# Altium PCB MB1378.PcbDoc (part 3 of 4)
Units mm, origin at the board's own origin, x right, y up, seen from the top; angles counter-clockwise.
Board outline 54.22 x 80.1 mm, 4 copper layers (Top Layer, L2-GND, L3, Bottom Layer), stack 0.771 mm thick; 206 components, 159 nets, 727 pads, 330 vias.
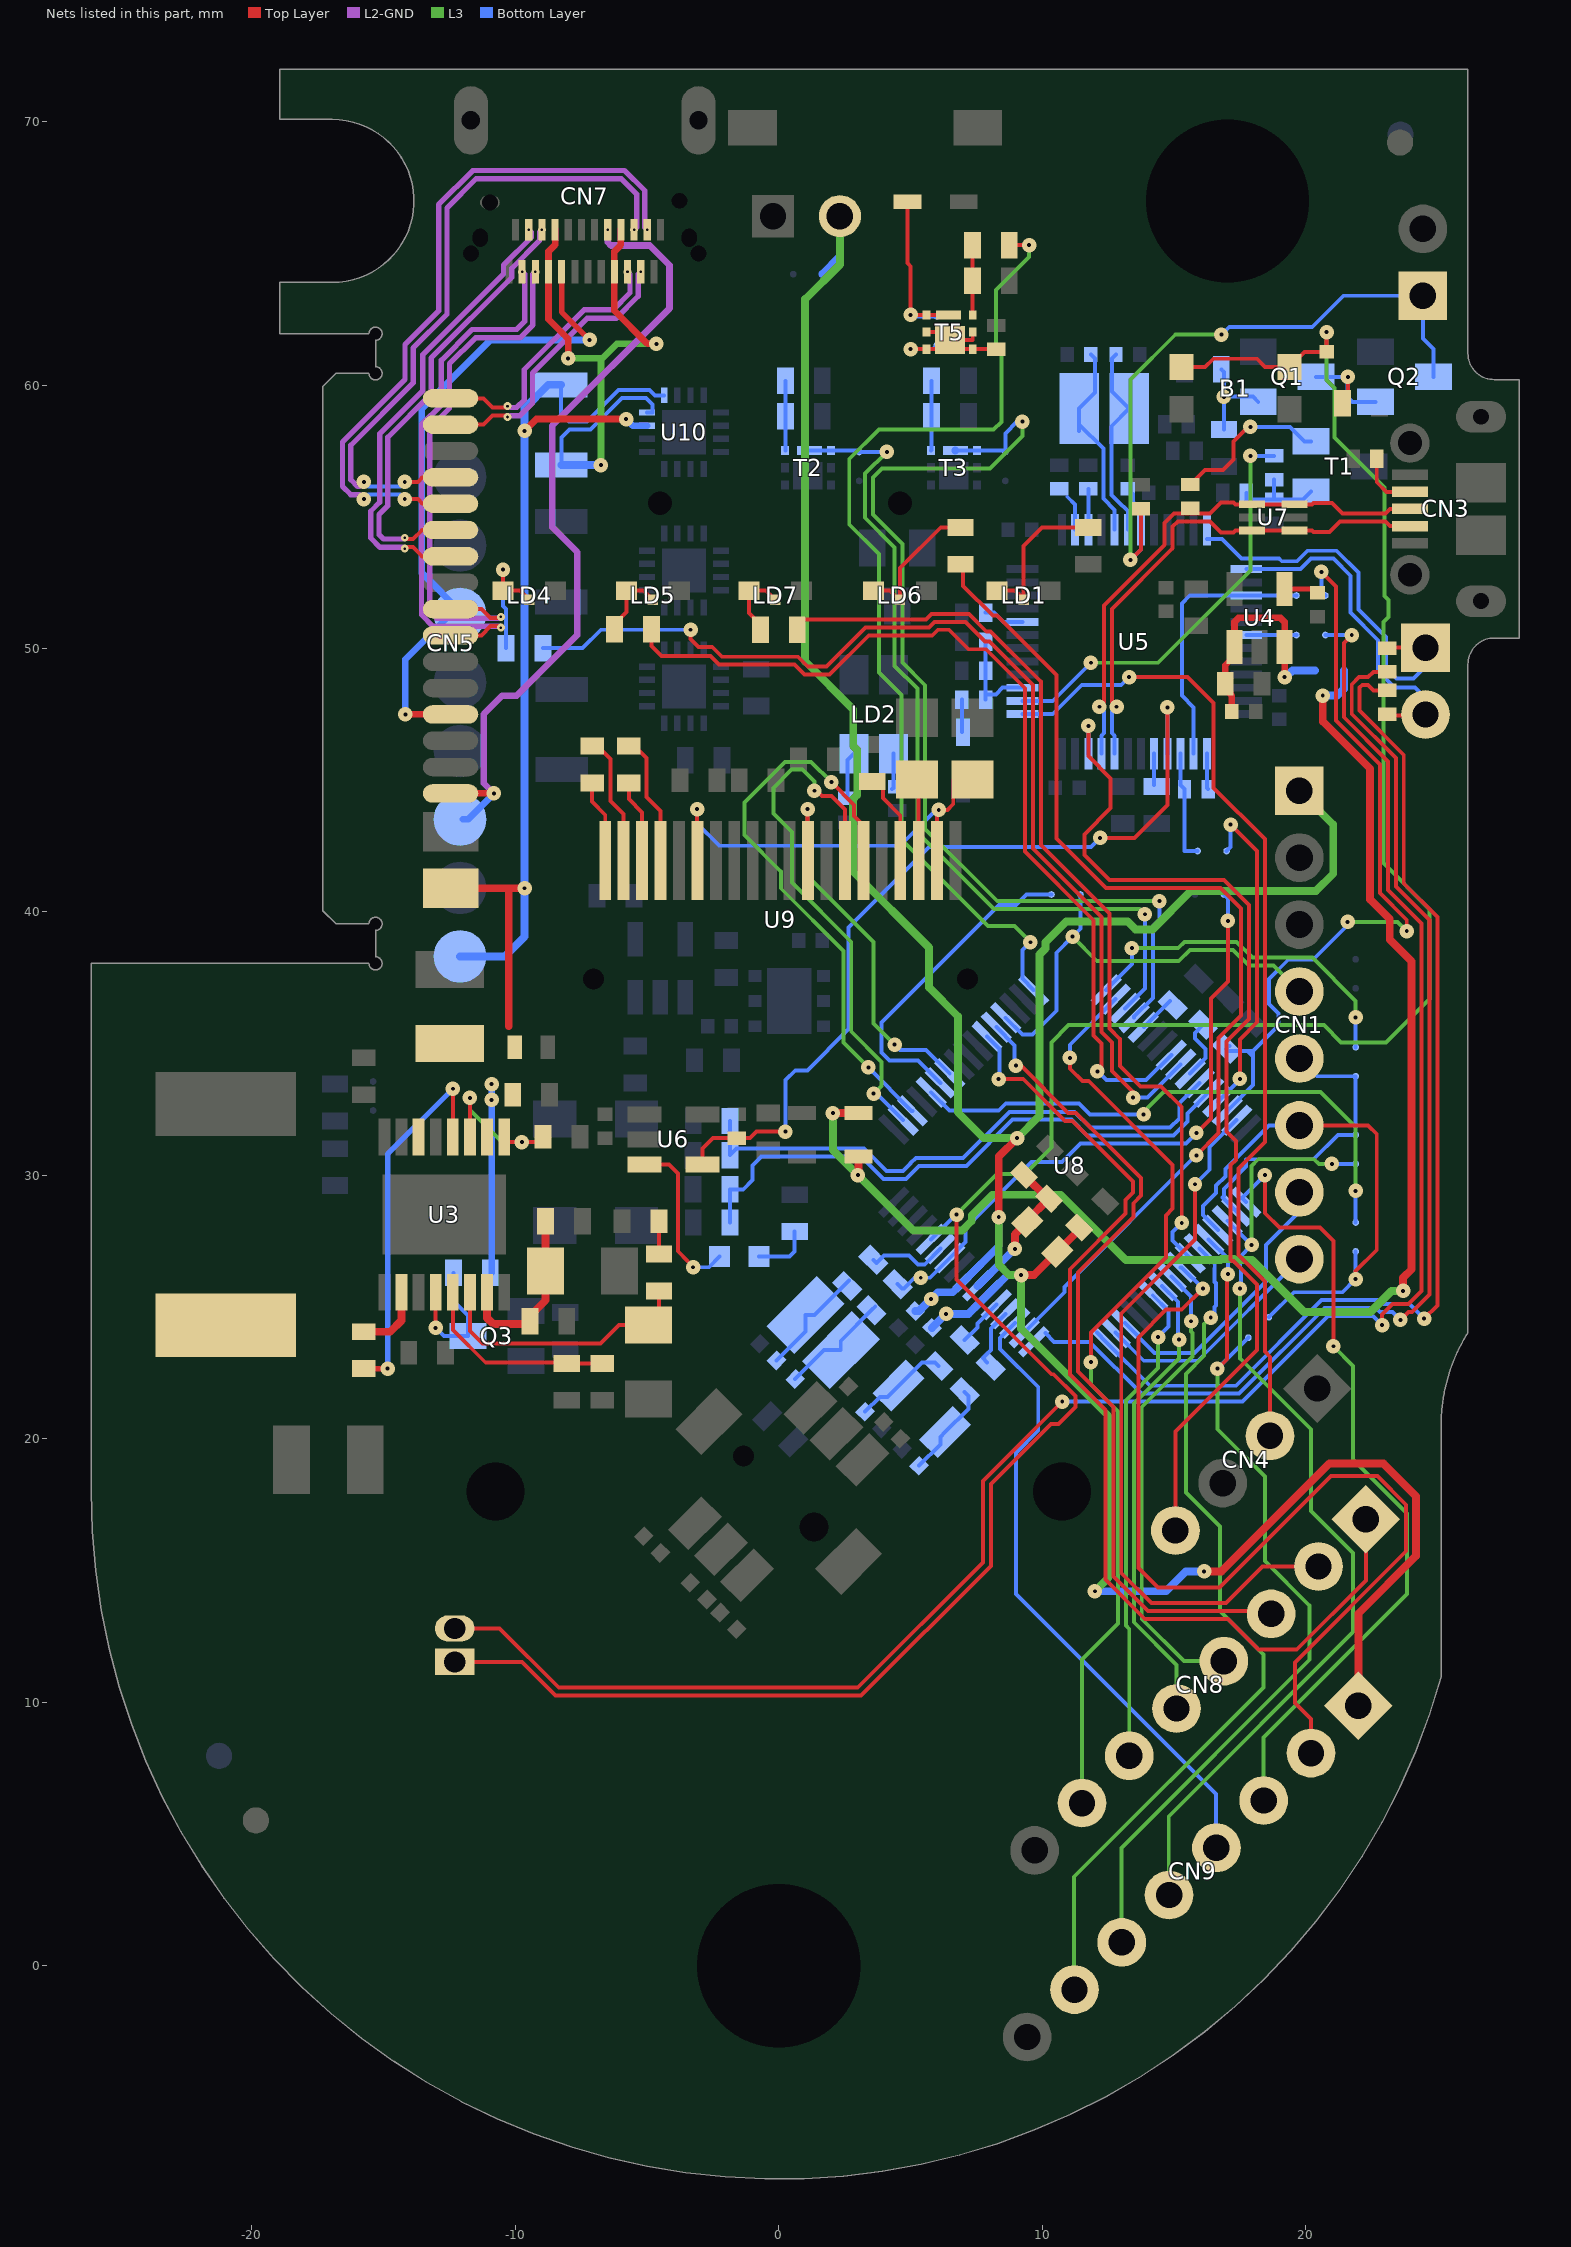
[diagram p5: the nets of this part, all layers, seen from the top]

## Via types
v1: diameter 0.55, hole 0.15, Top Layer to Bottom Layer, 308 vias
v2: diameter 0.3, hole 0.1, Top Layer to L2-GND, 22 vias

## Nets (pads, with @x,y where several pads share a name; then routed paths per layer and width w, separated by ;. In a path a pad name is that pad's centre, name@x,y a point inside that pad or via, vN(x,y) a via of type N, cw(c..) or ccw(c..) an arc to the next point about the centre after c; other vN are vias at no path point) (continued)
NetC9_1: C9.1 U3.12 | length 14.4
  Top Layer w0.15: U3.12@-12.372,31.462 v1(-12.372,33.287)
  Top Layer w0.2: C9.1@-15.747,22.662 v1(-14.847,22.662)
  Bottom Layer w0.2: v1(-14.847,22.662) -14.847,30.812 v1(-12.372,33.287)
NetC9_2: C9.2 L1.2 U3.2 | length 2.7
  Top Layer w0.3: C9.2@-15.747,24.062 -14.747,24.062 -14.322,24.487 U3.2@-14.322,25.562
NetC10_2: C10.2 R6.1 R10.2 U3.7 | length 6.8
  Top Layer w0.3: U3.7@-11.072,25.562 -11.072,24.587 -10.847,24.362 -9.472,24.362 -9.472,24.637 -8.847,25.262 C10.2@-8.847,26.362 R10.2@-8.847,28.262
NetC15_2: C15.2 R9.2 U3.5 | length 7.6
  Top Layer w0.15: U3.5@-12.372,25.562 -12.372,24.137 -11.122,22.887 -7.922,22.887 -7.897,22.862 C15.2@-6.697,22.862
NetC16_2: C16.2 U3.9 U3.11 | length 5.9
  Top Layer w0.15: U3.11@-11.722,31.462 v1(-11.722,32.937) ; U3.9@-10.372,31.262 C16.2@-8.897,31.262
  L3 w0.15: v1(-11.722,32.937) -11.722,32.487 -10.497,31.262 v1(-9.747,31.262)
NetC17_2: C17.2 R7.1 | length 1.2
  Top Layer w0.15: R7.1@-4.547,27.012 C17.2@-4.547,28.262
NetC18_2: C18.2 R7.2 U3.6 | length 10.1
  Top Layer w0.15: U3.6@-11.722,25.562 -11.722,24.087 -11.247,23.612 -6.768,23.612 -6.068,24.312 -5.697,24.312 -5.197,24.812 -4.697,24.812 -4.547,24.962 R7.2@-4.547,25.612
NetC21_1: C21.1 C22.2 SB1.2 U4.1 U4.3 | length 8.9
  Top Layer w0.25: C22.2@17.203,47.612 17.203,48.212 16.953,48.462 16.953,49.362 17.303,49.712 U4.1@17.303,50.062 17.303,51.012 17.453,51.162 19.053,51.162 19.203,51.012 U4.3@19.203,50.062 19.203,49.062 v1@19.303,48.962
  Bottom Layer w0.3: v1@19.303,48.962 19.503,49.162 SB1.2@20.353,49.162
  other v1: 19.203,48.912
NetC25_2: C25.2 U4.4 | length 1.3
  Top Layer w0.2: U4.4@19.303,52.262 C25.2@20.553,52.262
NetC34_1: C34.1 U9.2 | length 5.2
  Top Layer w0.15: C34.1@-7.087,46.299 -6.884,46.299 -6.387,45.802 -6.387,44.212 -5.887,43.712 U9.2@-5.887,41.949 U9.2@-5.887,41.749
NetC34_2: C34.2 U9.1 | length 3.4
  Top Layer w0.15: C34.2@-7.087,44.899 -7.087,44.187 -6.587,43.687 U9.1@-6.587,41.949 U9.1@-6.587,41.749
NetC35_1: C35.1 U9.3 | length 3.4
  Top Layer w0.15: C35.1@-5.687,44.899 -5.687,44.282 -5.187,43.782 U9.3@-5.187,41.949 U9.3@-5.187,41.749
NetC35_2: C35.2 U9.4 | length 5.2
  Top Layer w0.15: C35.2@-5.687,46.299 -5.474,46.299 -5.017,45.842 -5.017,44.357 -4.487,43.827 U9.4@-4.487,41.949 U9.4@-4.487,41.749
NetC36_1: C36.1 U9.6 U9.19 | length 17.2
  Top Layer w0.15: v1(-3.1,43.9) -3.1,41.962 U9.6@-3.087,41.949 U9.6@-3.087,41.749 ; U9.19@6.013,41.749 U9.19@6.013,41.949 6.013,43.818 6.07,43.875 v1(6.075,43.875) 6.399,43.875 6.625,44.101 6.625,44.987 C36.1@7.353,44.987
  Bottom Layer w0.15: v1(-3.1,43.9) -3.1,43.365 -2.247,42.512 4.603,42.512 5.965,43.875 v1(6.075,43.875)
NetC39_1: C39.1 R36.2 X2.1 | length 3.6
  Bottom Layer w0.15: C39.1@5.325,18.978 6.138,19.791 6.138,20.074 X2.1@6.315,20.251 7.199,21.135 7.199,21.63 R36.2@7.057,21.771
NetC40_1: C40.1 R39.2 X2.2 | length 3.6
  Bottom Layer w0.15: C40.1@3.274,21.029 3.84,21.594 4.123,21.594 5.431,22.902 5.926,22.902 R39.2@6.067,22.761
NetC41_1: C41.1 U9.18 | length 3.2
  Top Layer w0.15: U9.18@5.313,41.749 C41.1@5.313,44.974
NetC42_1: C42.1 R41.2 X3.2 | length 4.4
  Bottom Layer w0.15: C42.1@0.623,22.266 1.719,23.362 X3.2@2.355,23.362 2.355,23.716 R41.2@3.522,24.882 R41.2@3.663,25.024
NetC43_1: C43.1 R44.2 X3.1 | length 4.4
  Bottom Layer w0.15: C43.1@-0.084,22.973 1.012,24.069 X3.1@1.012,24.706 1.365,24.706 R44.2@2.673,26.014
NetD3_1: D3.1 SB10.2 T5.4 T5.7 | length 6.8
  Top Layer w0.15: D3.1@4.883,66.962 4.883,64.632 5.003,64.512 v1(5.003,62.662) T5.4@5.615,62.662 T5.7@6.44,62.662
  Bottom Layer w0.15: v1(5.003,62.662) 5.053,62.612 SB10.2@6.003,62.612
NetD4_2: D4.2 R12.2 | length 1.2
  Bottom Layer w0.15: D4.2@6.953,46.832 R12.2@6.953,48.062
NetD5_2: D5.2 D6.2 SB1.1 | length 54.6
  Top Layer w0.3: v1(2.053,32.362) D5.2@3.023,32.362 ; v1(3.003,30.012) 3.023,30.032 D6.2@3.023,30.712 ; v1(20.653,48.212) 20.653,47.236 22.453,45.436 22.453,40.476 23.195,39.733 23.195,38.95 24.028,38.117 24.028,26.437 23.703,26.112 v1(23.703,25.612)
  L3 w0.3: v1(2.053,32.362) 2.053,30.962 v1(3.003,30.012) 5.115,27.9 6.953,27.9 7.328,28.274 7.328,28.478 8.112,29.262 10.703,29.262 13.178,26.787 16.774,26.787 16.812,26.825 17.288,26.825 17.326,26.787 17.963,26.787 19.938,24.812 22.466,24.812 23.266,25.612 v1(23.703,25.612)
  Bottom Layer w0.3: v1(20.653,48.212) 21.203,48.212 21.453,48.462 SB1.1@21.453,49.162
NetJP2_2: JP2.2 SB4.2 | length 73.5
  Top Layer w0.15: JP2.2@-12.3,12.8 -10.6,12.8 -8.35,10.55 3,10.55 7.75,15.3 7.75,18.4 v1(10.762,21.412) ; v1(21.753,50.512) 21.453,50.212 21.453,47.391 23.128,45.716 23.128,40.839 24.403,39.564 24.403,25.605 23.91,25.112 23.296,25.112 22.903,24.719 v1(22.903,24.312)
  Bottom Layer w0.15: v1(10.762,21.412) 17.601,21.412 20.851,24.662 22.553,24.662 v1(22.903,24.312) ; SB4.2@20.753,50.512 v1(21.753,50.512)
NetLD1_1: LD1.1 R3.1 | length 5.9
  Top Layer w0.15: LD1.1@8.293,52.199 8.966,52.199 LD1.1@9.293,51.872 ; LD1.1@9.293,51.849 LD1.1@9.293,51.872 ; R3.1@11.75,54.6 10,54.6 9.293,53.893 LD1.1@9.293,51.872
NetLD2_2: LD2.2 R24.1 | length 1.8
  Bottom Layer w0.15: R24.1@2.603,44.312 2.603,45.762 LD2.2@2.853,46.012
NetLD2_3: LD2.3 R26.1 | length 1.4
  Bottom Layer w0.15: R26.1@4.303,44.662 4.353,44.712 LD2.3@4.353,46.012
NetLD3_1: LD3.1 R31.2 | length 2.2
  Bottom Layer w0.15: LD3.1@-0.747,26.912 0.403,26.912 0.603,27.112 R31.2@0.603,27.862
NetLD3_2: LD3.2 U6.3 | length 6.1
  Top Layer w0.15: U6.3@-5.097,30.412 -4.166,30.412 -3.822,30.069 -3.822,27.119 -3.457,26.753
  Bottom Layer w0.15: v1(-3.247,26.512) -2.647,26.512 LD3.2@-2.247,26.912
NetLD4_1: LD4.1 R32.1 | length 4.9
  Top Layer w0.15: v1(-10.467,52.992) LD4.1@-10.467,52.199 -9.817,52.199 LD4.1@-9.481,51.862
  Bottom Layer w0.15: v1(-10.467,52.992) -10.467,51.612 -10.347,51.492 R32.1@-10.347,50.012
NetLD5_1: LD5.1 R33.1 | length 2.6
  Top Layer w0.15: R33.1@-6.247,50.912 -5.777,51.382 LD5.1@-5.777,52.199 -5.134,52.199 LD5.1@-4.797,51.862
NetLD6_1: LD6.1 R52.1 | length 5.3
  Top Layer w0.15: LD6.1@3.602,52.199 4.216,52.199 4.553,51.862 LD6.1@4.602,51.862 ; LD6.1@4.602,51.849 LD6.1@4.602,51.862 ; R52.1@6.9,54.6 6.15,54.6 4.602,53.052 LD6.1@4.602,51.862
NetLD7_1: LD7.1 R61.1 | length 2.9
  Top Layer w0.15: R61.1@-0.697,50.712 -0.697,50.912 -1.137,51.352 LD7.1@-1.137,52.199 -0.484,52.199 LD7.1@-0.097,51.812
NetQ1_1: Q1.1 R42.2 R43.2 | length 3.7
  Bottom Layer w0.15: R43.2@16.8,60.6 16.903,60.497 v1@16.903,59.612 ; R42.2@16.903,58.312 v1(16.903,59.55) v1@16.903,59.612 ; Q1.1@18.203,59.362 18.003,59.562 16.953,59.562 v1@16.903,59.612
NetQ1_3: Q1.3 Q2.1 R51.1 | length 4.2
  Top Layer w0.15: R51.1@21.403,59.312 21.603,59.512 v1(21.603,60.312)
  Bottom Layer w0.15: Q1.3@20.403,60.312 v1(21.603,60.312) 21.6,60.31 21.6,59.55 21.788,59.362 Q2.1@22.653,59.362
NetQ3_3: Q3.3 R8.1 U3.4 | length 5.3
  Top Layer w0.15: v1(-13.022,24.212) U3.4@-13.022,25.562
  Bottom Layer w0.15: v1(-13.022,24.212) -12.71,23.9 Q3.3@-11.8,23.9 -11.8,24.675 -12.35,25.225 R8.1@-12.35,26.3
NetR14_2: R14.2 U5.44 | length 1.5
  Bottom Layer w0.15: R14.2@7.853,51.362 8.177,51.362 8.527,51.012 U5.44@9.253,51.012
NetR15_1: R15.1 U5.2 | length 1.4
  Bottom Layer w0.15: 10.953,55.762 11.253,55.462 U5.2@11.253,54.512
NetR16_2: R16.2 U5.3 | length 1.6
  Bottom Layer w0.15: U5.3@11.753,54.512 R16.2@11.753,56.062
NetR18_1: R18.1 U5.29 | length 1.2
  Bottom Layer w0.15: R18.1@14.253,44.812 U5.29@14.253,46.012
NetR25_1: R25.1 R27.2 R28.2 T1.1 | length 3.6
  Bottom Layer w0.15: R28.2@17.753,55.912 17.753,55.662 R27.2@18.803,55.662 ; R25.1@18.803,56.412 R27.2@18.803,55.662 ; T1.1@20.203,55.962 19.903,55.662 R27.2@18.803,55.662
NetR29_2: R29.2 T1.2 | length 6.1
  Top Layer w0.15: R29.2@15.628,56.226 16.174,56.773 16.863,56.773 17.268,57.177 17.268,57.866 17.814,58.412 v1(17.903,58.412)
  Bottom Layer w0.15: v1(17.903,58.412) 19.403,58.412 19.953,57.862 T1.2@20.203,57.862
NetR35_2: R35.2 U8.37 | length 1.4
  Bottom Layer w0.15: U8.37@13.871,35.63 R35.2@14.858,36.617
NetR38_2: R38.2 U8.42 | length 2.4
  Bottom Layer w0.15: U8.42@15.613,33.863 16.2,34.449 16.2,34.8 16,35 15.8,35.2 15.8,35.41 R38.2@16.108,35.717
NetR40_2: R40.2 U9.17 | length 3.9
  Top Layer w0.15: R40.2@3.55,44.95 3.955,44.95 3.955,44.325 4.613,43.667 U9.17@4.613,41.949 U9.17@4.613,41.749
NetR52_2: R52.2 U8.2 | length 39.6
  Top Layer w0.15: R52.2@6.9,53.2 7.003,53.097 7.003,52.374 8.127,51.25 8.288,51.25 10.55,48.988 10.55,42.791 12.428,40.912 16.778,40.912 17.553,40.138 17.553,36.061 16.703,35.211 16.703,31.612 v1(15.853,30.762)
  Bottom Layer w0.15: U8.2@9.32,24.034 10.849,25.562 10.849,25.766 15.845,30.762 v1(15.853,30.762)
NetR55_1: R55.1 R62.2 T5.3 | length 2.6
  Top Layer w0.15: T5.3@7.353,62.675 R55.1@7.353,63.962 R62.2@7.353,65.312
NetR56_1: R56.1 SB10.1 T5.1 T5.2 T5.5 T5.6 T5.8 | length 6.7
  Top Layer w0.15: v1(5.003,61.362) T5.6@5.615,61.362 T5.1@7.365,61.362 R56.1@8.253,61.362 ; T5.5@5.615,62.012 6.503,62.012 T5.8@6.503,61.712 7.365,61.712 T5.2@7.365,62.012
  Bottom Layer w0.15: v1(5.003,61.362) 5.853,61.362 SB10.1@6.003,61.512
NetR57_1: R57.1 R59.2 T2.3 | length 2.6
  Bottom Layer w0.15: T2.3@0.253,57.525 R57.1@0.253,58.812 R59.2@0.253,60.162
NetR58_1: R58.1 R60.2 T3.3 | length 2.7
  Bottom Layer w0.15: T3.3@5.778,57.512 5.803,57.537 R58.1@5.803,58.812 R60.2@5.803,60.162
NRST: B1.1 B1.3 C44.2 JP2.1 U8.12 | length 99.1
  Top Layer w0.15: JP2.1@-12.3,11.53 -9.754,11.53 -8.474,10.25 3.124,10.25 8.05,15.176 8.05,18.276 10.337,20.562 10.62,20.562 11.262,21.205 11.262,21.62 10.432,22.45 10.35,22.45 6.753,26.047 v1(6.753,28.512) ; B1.3@15.288,60.687 16.187,60.687 16.5,61 18.15,61 18.463,60.687 B1.1@19.388,60.687 19.963,61.262 C44.2@20.803,61.262 v1(20.803,62.012)
  L3 w0.15: v1(6.753,28.512) 8.29,30.05 9.35,30.05 10.35,31.05 10.35,35.05 11,35.7 20.7,35.7 21.35,35.05 23.05,35.05 24.703,36.703 24.703,40.097 22.95,41.85 22.95,47.979 22.953,47.982 22.953,51.003 23.153,51.203 23.153,51.837 22.988,52.002 22.988,56.12 21.103,58.005 21.103,59.897 20.803,60.197 v1(20.803,62.012)
  Bottom Layer w0.15: U8.12@5.785,27.569 v1@6.74,28.525
OSC_IN: C20.1 U5.5 X1.2 | length 7.8
  Bottom Layer w0.15: X1.2@11.403,58.262 X1.2@11.403,58.512 ; C20.1@11.853,61.162 12.003,61.012 12.003,59.712 X1.2@11.403,59.112 X1.2@11.403,58.512 ; U5.5@12.753,54.512 12.753,55.263 12.328,55.688 12.328,57.587 X1.2@11.403,58.512
OSC_OUT: C19.1 U5.6 X1.1 | length 7.5
  Bottom Layer w0.15: C19.1@12.803,61.162 12.653,61.012 12.653,59.762 X1.1@13.303,59.112 12.628,58.437 12.628,55.834 12.879,55.582 12.883,55.582 13.253,55.212 U5.6@13.253,54.512
PA4: SB12.1 U8.21 | length 21.3
  L3 w0.15: v1(13.853,32.312) 13.853,32.412 14.603,33.162 20.575,33.162 21.903,31.835 v1(21.903,29.412)
  Bottom Layer w0.15: U8.21@5.785,33.155 6.478,32.462 8.353,32.462 8.618,32.728 11.403,32.728 11.818,32.312 v1(13.853,32.312) ; SB12.1@21.903,28.212 v1(21.903,29.412)
PA5: SB11.1 U8.22 | length 12.3
  Bottom Layer w0.15: U8.22@6.138,33.509 5.285,34.362 4.203,34.362 3.903,34.662 3.903,35.803 8.362,40.262 9.003,40.262 9.403,40.662 SB11.1@10.353,40.662
PA15: CN8.2 U8.47 | length 27.5
  Top Layer w0.15: v1(15.803,29.662) 15.803,27.561 13.003,24.761 13.003,14.903 14.144,13.762 16.981,13.762 18.37,15.151 CN8.2@20.491,15.151
  Bottom Layer w0.15: v1(15.803,29.662) 16.353,30.212 16.353,31.066 U8.47@17.381,32.095
PB0: CN8.1 U8.27 | length 39.6
  Top Layer w0.15: v1(8.35,33.65) 9.282,33.65 10.864,32.069 11.153,32.069 13.453,29.77 13.453,29.355 13.163,29.066 13.163,28.548 11.053,26.437 11.053,22.438 12.403,21.088 12.403,14.655 13.895,13.162 17.053,13.162 18.215,12 19.666,12 22.287,14.621 CN8.1@22.287,16.947
  Bottom Layer w0.15: U8.27@7.906,35.277 8.378,34.804 8.378,33.678 v1(8.35,33.65)
PB1: CN8.3 U8.28 | length 31.5
  Top Layer w0.15: v1(9.003,34.162) 9.194,34.162 10.988,32.369 11.278,32.369 13.753,29.894 13.753,29.231 13.463,28.942 13.463,28.423 11.353,26.312 11.353,22.562 12.703,21.212 12.703,14.779 14.019,13.462 18.587,13.462 CN8.3@18.695,13.354
  Bottom Layer w0.15: U8.28@8.26,35.63 8.952,34.937 8.952,34.213 v1(9.003,34.162)
PB2: CN1.4 SB11.2 U8.29 | length 17.2
  L3 w0.15: v1(11.153,39.062) 12.086,38.129 15.179,38.129 15.612,38.562 17.253,38.562 17.853,37.962 18.779,37.962 CN1.4@19.763,36.979
  Bottom Layer w0.15: U8.29@8.613,35.984 9.253,35.344 9.635,35.344 10.54,36.25 10.54,38.45 v1(11.153,39.062) 11.453,39.362 SB11.2@11.453,40.662
PB3: CN8.4 U8.57 | length 17.9
  L3 w0.15: v1(15.653,24.462) 15.653,24.062 15.703,24.012 15.703,23.131 13.781,21.209 13.781,13.158 15.381,11.558 CN8.4@16.899,11.558
  Bottom Layer w0.15: U8.57@14.906,26.155 15.653,25.409 v1(15.653,24.462)
PB4: CN8.5 U8.58 | length 17.7
  L3 w0.15: CN8.5@15.103,9.762 15.103,11.412 13.481,13.034 13.481,21.333 15.203,23.055 v1(15.203,23.762)
  Bottom Layer w0.15: U8.58@14.553,25.802 15.153,25.202 15.153,23.812 v1(15.203,23.762)
PB5: CN8.6 U8.59 | length 18.5
  L3 w0.15: CN8.6@13.307,7.966 13.307,12.784 13.181,12.91 13.181,21.458 14.403,22.68 v1(14.403,23.862)
  Bottom Layer w0.15: U8.59@14.199,25.448 14.803,24.845 14.803,24.262 v1(14.403,23.862)
PB8: CN1.7 U8.62 | length 10.9
  Bottom Layer w0.15: U8.62@13.139,24.387 14.263,23.262 15.783,23.262 18.492,25.971 18.492,27.351 19.763,28.623 CN1.7@19.763,29.359
PB9: CN1.8 U8.63 | length 9
  Bottom Layer w0.15: U8.63@12.785,24.034 13.856,22.962 15.907,22.962 CN1.8@19.763,26.819
PB13: SB13.1 U8.33 | length 13.3
  L3 w0.15: v1(13.403,38.629) 15.167,38.629 15.4,38.862 17.377,38.862 17.977,38.262 20.258,38.262 21.903,36.617 v1@21.903,36
  Bottom Layer w0.15: U8.33@12.431,37.045 13.403,38.016 v1(13.403,38.629) ; SB13.1@21.903,34.862 v1@21.903,36
  other v1: 21.9,36
PB14: CN8.7 U8.34 | length 35.3
  Top Layer w0.15: v1(11.053,34.462) 11.053,34.047 11.525,33.575 11.769,33.575 14.953,30.391 14.953,28.734 14.703,28.484 14.703,26.885 11.853,24.035 v1(11.853,22.912)
  L3 w0.15: CN8.7@11.51,6.17 11.51,11.62 12.881,12.991 12.881,21.034 11.853,22.062 v1(11.853,22.912)
  Bottom Layer w0.15: v1(11.053,34.462) 11.053,34.959 U8.34@12.785,36.691
PC9: CN9.3 U8.49 | length 30.6
  Top Layer w0.15: v1(18.453,30.012) 18.453,28.562 19.003,28.012 20.553,28.012 21.053,27.512 v1(21.053,23.512)
  L3 w0.15: CN9.3@18.399,6.27 18.399,8.658 23.853,14.112 23.853,17.162 21.803,19.212 21.803,22.762 v1(21.053,23.512)
  Bottom Layer w0.15: U8.49@17.735,28.984 17.579,29.139 v1(18.453,30.012)
PC13: CN9.4 U8.3 | length 24.2
  Bottom Layer w0.15: U8.3@8.967,24.387 8.403,23.823 8.403,23.412 9.853,21.962 9.853,20.312 9.003,19.462 9.003,14.112 16.603,6.512 CN9.4@16.603,4.474
PC14: R36.1 U8.4 | length 2.3
  Bottom Layer w0.15: R36.1@7.906,22.902 7.749,23.059 8.053,23.362 8.053,24.18 U8.4@8.613,24.741
PC15: R39.1 U8.5 | length 1.8
  Bottom Layer w0.15: R39.1@7.057,23.751 7.538,24.232 7.538,24.373 U8.5@8.26,25.094
PD0: CN1.5 SB13.2 SB14.1 U8.50 | length 11.5
  Bottom Layer w0.15: U8.50@17.381,28.63 16.853,29.158 16.903,29.207 16.903,29.49 17.745,30.333 17.745,30.612 20.303,30.612 21.228,31.537 SB14.1@21.903,31.537 ; CN1.5@19.763,34.439 20.439,33.762 SB13.2@21.903,33.762 21.903,31.812
PD1: CN9.5 SB14.2 U8.51 | length 38
  L3 w0.15: CN9.5@14.807,2.678 14.807,5.666 21.803,12.662 21.803,15.662 20.203,17.262 20.203,20.362 17.509,23.056 v1(17.509,25.7) ; v1(17.953,27.362) 17.953,30.362 18.203,30.612 20.328,30.612 20.503,30.437 v1(21.003,30.437)
  Bottom Layer w0.15: U8.51@17.028,28.276 17.953,27.351 17.509,26.908 17.509,26.498 17.55,26.457 17.55,25.741 v1(17.509,25.7) ; v1(21.003,30.437) SB14.2@21.903,30.437
PD2: CN1.6 SB12.2 SB15.1 U8.52 | length 20.3
  Top Layer w0.15: CN1.6@19.763,31.899 22.366,31.899 22.703,31.562 22.703,27.162 21.903,26.362 v1(21.903,26.062)
  Bottom Layer w0.15: U8.52@16.674,27.923 16.103,28.494 16.103,28.831 16.603,29.331 16.603,29.614 16.953,29.964 16.953,30.244 18.607,31.899 CN1.6@19.763,31.899 ; SB15.1@18.606,24.616 19.553,25.562 21.403,25.562 v1(21.903,26.062) SB12.2@21.903,27.112
PD3: CN9.6 SB15.2 U8.53 | length 33.2
  Top Layer w0.15: v1(16.653,22.662) 17.009,23.019 17.009,26.209 v1(17.05,26.25)
  L3 w0.15: CN9.6@13.01,0.882 13.01,4.47 20.153,11.612 20.153,13.662 18.453,15.362 18.453,18.562 16.653,20.362 v1(16.653,22.662)
  Bottom Layer w0.15: U8.53@16.321,27.569 17.05,26.84 v1(17.05,26.25) ; v1(16.653,22.662) SB15.2@17.828,23.838
PD4: CN9.7 U8.54 | length 33.1
  L3 w0.15: CN9.7@11.214,-0.914 11.214,3.374 18.403,10.562 18.403,11.812 16.753,13.462 16.753,16.662 15.453,17.962 15.453,22.457 16.153,23.157 16.153,24.353 v1(16.4,24.6)
  Bottom Layer w0.15: U8.54@15.967,27.216 16.553,26.63 16.553,26.46 16.55,26.457 16.55,25.957 16.6,25.907 16.6,25.05 16.55,25 16.55,24.75 v1(16.4,24.6)
PD5: R61.2 U8.55 | length 35.8
  Top Layer w0.15: R61.2@0.703,50.712 0.703,51.1 5.585,51.1 5.797,51.312 7.216,51.312 7.878,50.65 8.04,50.65 9.95,48.74 9.95,42.542 12.553,39.94 12.553,35.568 12.953,35.168 12.953,34.155 13.734,33.374 14.515,33.374 15.3,32.589 v1(15.3,28.2)
  Bottom Layer w0.15: v1(15.3,28.2) 14.95,27.85 14.95,27.526 U8.55@15.613,26.862
PD6: CN9.2 U8.56 | length 37.2
  Top Layer w0.15: v1(16.1,25.7) 15.3,24.9 14.703,24.9 13.653,23.85 13.653,15.102 14.392,14.362 16.733,14.362 20.958,18.587 22.728,18.587 23.82,17.495 23.82,15.73 19.603,11.512 19.603,9.962 20.207,9.358 CN9.2@20.207,8.066
  Bottom Layer w0.15: U8.56@15.26,26.509 15.291,26.509 v1(16.1,25.7)
PD8: R33.2 U8.40 | length 36
  Top Layer w0.15: R33.2@-4.831,50.733 -4.831,50.096 -4.447,49.712 -2.597,49.712 -2.272,49.387 0.603,49.387 0.978,49.012 1.934,49.012 3.417,50.495 5.828,50.495 6.045,50.712 6.47,50.712 7.21,49.972 7.869,49.972 9.35,48.491 9.35,42.288 11.953,39.685 11.953,35.314 12.253,35.014 12.253,34.103 v1(12.1,33.95)
  Bottom Layer w0.15: v1(12.1,33.95) 12.438,33.612 13.949,33.612 U8.40@14.906,34.57
PD9: R32.2 U8.41 | length 40.9
  Top Layer w0.15: v1(-3.347,50.712) -3.347,50.362 -3.047,50.062 -2.523,50.062 -2.148,49.687 0.728,49.687 1.103,49.312 1.81,49.312 3.297,50.8 5.709,50.8 5.921,51.012 7.092,51.012 7.832,50.272 7.993,50.272 9.65,48.615 9.65,42.412 12.253,39.809 12.253,35.444 12.653,35.044 12.653,33.962 13.45,33.165 v1(13.45,32.95)
  Bottom Layer w0.15: R32.2@-8.947,50.012 -7.447,50.012 -6.747,50.712 v1(-3.347,50.712) ; v1(13.45,32.95) 13.994,32.95 U8.41@15.26,34.216
PF0: R41.1 SB5.1 U8.10 | length 23.7
  Top Layer w0.15: v1(15.853,31.612) 16.403,32.162 16.403,36.712 17.053,37.362 v1(17.053,39.662)
  Bottom Layer w0.15: R41.1@4.512,25.872 4.672,25.712 4.753,25.712 5.153,26.112 v1@5.272,26.112 ; v1(5.391,26.112) 5.742,26.112 U8.10@6.492,26.862 7.092,27.462 7.092,28.002 9.603,30.512 10.753,30.512 11.453,31.212 15.453,31.212 v1(15.853,31.612) ; SB5.1@16.903,40.662 17.053,40.512 v1(17.053,39.662)
PF1: R44.1 U8.11 | length 3.1
  Bottom Layer w0.15: R44.1@3.593,26.792 3.707,26.677 3.996,26.966 4.949,26.966 5.294,26.621 5.544,26.621 U8.11@6.138,27.216
PWR_ENn: R30.1 U5.28 U6.4 | length 32.5
  Top Layer w0.15: U6.4@-2.897,30.412 -2.897,31.012 -2.497,31.412 -1.097,31.412 -0.847,31.662 v1(0.253,31.662) ; v1(12.203,42.812) 13.503,42.812 14.753,44.062 v1(14.753,47.762)
  Bottom Layer w0.15: v1(0.253,31.662) 0.253,33.612 0.628,33.987 1.084,33.987 2.653,35.556 2.653,39.412 5.703,42.462 11.853,42.462 v1(12.203,42.812) ; U5.28@14.753,46.012 v1(14.753,47.762)
PWR_EXT: R11.2 R12.1 R13.1 U5.39 | length 3.7
  Bottom Layer w0.15: R12.1@7.853,48.062 R12.1@7.853,48.262 ; R11.2@7.853,50.262 R12.1@7.853,48.262 ; U5.39@9.253,48.512 8.503,48.512 8.253,48.262 R12.1@7.853,48.262
RD_CC1: R62.1 U8.32 | length 38.5
  Top Layer w0.15: R62.1@8.753,65.312 v1(9.503,65.312)
  L3 w0.15: v1@9.403,38.762 9.403,39.005 8.945,39.462 7.951,39.462 4.66,42.754 4.66,48.232 3.803,49.09 3.803,53.59 2.678,54.715 2.678,57.187 3.803,58.312 8.16,58.312 8.453,58.605 8.453,61.288 8.253,61.488 8.253,63.612 9.503,64.862 v1(9.503,65.312)
  Bottom Layer w0.15: v1@9.403,38.762 9.49,38.85 v1(9.55,38.85) 9.25,38.55 9.25,37.468 U8.32@9.674,37.045
RST_DISP: U8.23 U9.12 | length 15
  Top Layer w0.15: v1(1.1,43.9) 1.1,41.962 U9.12@1.113,41.949 U9.12@1.113,41.749
  L3 w0.15: v1(1.1,43.9) 1.1,41.365 3.603,38.862 3.603,35.762 v1(4.403,34.962)
  Bottom Layer w0.15: v1(4.403,34.962) 4.603,34.762 5.592,34.762 U8.23@6.492,33.863
RX1_N: CN5.B10 CN7.B10 | length 25.4
  Top Layer w0.152: v1(-14.197,56.329) -13.703,56.329 -13.533,56.499 CN5.B10@-12.457,56.499 CN5.B10@-12.407,56.499
  L2-GND w0.202: v1(-15.747,56.329) -15.921,56.155 -15.99,56.155 -16.247,56.412 -16.247,57.712 -13.877,60.083 -13.877,61.409 -12.597,62.689 -12.597,66.722 -11.483,67.836 -5.983,67.836 -5.396,67.249 -5.396,65.993 v2(-5.49,65.899)
  Bottom Layer w0.152: v1(-15.747,56.329) -15.57,56.151 -14.375,56.151 v1(-14.197,56.329)
RX1_P: CN5.B11 CN7.B11 | length 27
  Top Layer w0.152: v1(-14.197,55.669) -13.703,55.669 -13.533,55.499 CN5.B11@-12.457,55.499 CN5.B11@-12.407,55.499
  L2-GND w0.202: v1(-15.747,55.669) -15.921,55.843 -16.247,55.843 -16.559,56.155 -16.559,57.842 -14.189,60.212 -14.189,61.538 -12.909,62.818 -12.909,66.851 -11.612,68.148 -5.854,68.148 -5.084,67.378 -5.084,65.993 v2(-4.99,65.899)
  Bottom Layer w0.152: v1(-15.747,55.669) -15.57,55.846 -14.375,55.846 v1(-14.197,55.669)
RX2_N: CN5.A10 CN7.A10 | length 20.4
  Top Layer w0.152: CN5.A10@-12.407,51.499 -11.281,51.499 -10.933,51.151 -10.6,51.151 v2(-10.547,51.204)
  L2-GND w0.202: v2(-10.547,51.204) -10.596,51.155 -12.99,51.155 -13.247,51.412 -13.247,58.371 -12.497,59.121 -12.497,60.812 -11.514,61.796 -9.823,61.796 -9.334,62.285 -9.334,64.205 v2(-9.24,64.299)
RX2_P: CN5.A11 CN7.A11 | length 20.9
  Top Layer w0.152: CN5.A11@-12.407,50.499 -11.281,50.499 -10.933,50.846 -10.6,50.846 v2(-10.547,50.794)
  L2-GND w0.202: v2(-10.547,50.794) -10.596,50.843 -13.119,50.843 -13.559,51.283 -13.559,58.5 -12.809,59.25 -12.809,60.942 -11.643,62.108 -10.952,62.108 -10.947,62.112 -9.947,62.112 -9.646,62.414 -9.646,64.205 v2(-9.74,64.299)
SBU1: CN5.A8 CN7.A8 SBU1.1 | length 25.6
  Top Layer w0.202: CN7.A8@-8.24,64.299 -8.24,62.774 v1(-7.178,61.712)
  Top Layer w0.25: v1(-14.177,47.499) CN5.A8@-12.457,47.499
  Bottom Layer w0.25: v1(-14.177,47.499) -14.177,49.583 -12.447,51.312 SBU1.1@-12.097,51.312 -11.997,51.312 -13.547,52.862 -13.547,59.112 -10.947,61.712 v1(-7.178,61.712)
SBU2: CN5.B8 CN7.B8 SBU2.1 | length 30.7
  Top Layer w0.25: CN5.B8@-12.457,44.499 v1(-10.811,44.499)
  L2-GND w0.25: v1(-10.811,44.499) -11.197,44.885 -11.197,47.512 -10.497,48.212 -9.947,48.212 -7.647,50.512 -7.647,53.662 -8.597,54.612 -8.597,58.462 -4.147,62.912 -4.147,64.547 -4.899,65.299 -6.365,65.299 -6.49,65.424 v2(-6.49,65.899)
  Bottom Layer w0.25: SBU2.1@-11.997,43.512 -11.797,43.512 v1(-10.811,44.499)
SMPS_ON: R2.1 R5.2 U8.44 | length 22.7
  Bottom Layer w0.15: R5.2@-1.853,28.218 R2.1@-1.853,29.467 -1.347,29.467 -0.997,29.817 -0.997,30.37 -0.655,30.712 3.121,30.712 3.971,29.862 4.834,29.862 5.303,30.331 5.303,30.338 5.327,30.362 7.127,30.362 8.877,32.112 11.11,32.112 11.71,31.512 14.984,31.512 15.513,32.042 15.513,32.348 U8.44@16.321,33.155
SPI1_MOSI: U8.19 U9.15 | length 22.1
  Top Layer w0.15: v1(1.995,44.925) 2.855,44.065 2.855,43.65 3.213,43.292 U9.15@3.213,41.949
  L3 w0.15: v1(1.995,44.925) 1.22,45.7 0.243,45.7 -1.3,44.157 -1.3,42.916 0.078,41.539 0.078,40.9 2.453,38.525 2.453,35.047 v1(3.4,34.1)
  Bottom Layer w0.15: v1(3.4,34.1) 3.4,34.093 5.045,32.448 U8.19@5.078,32.448
SPI1_SCK: U8.18 U9.14 | length 20.7
  Top Layer w0.15: v1(1.35,44.6) 1.45,44.6 1.65,44.4 2.007,44.4 2.513,43.894 U9.14@2.513,41.949
  L3 w0.15: v1(1.35,44.6) 1.35,44.957 0.907,45.4 0.493,45.4 -0.2,44.707 -0.2,43.743 0.5,43.043 0.5,41.116 2.753,38.864 2.753,35.455 3.9,34.307 3.9,33.4 v1(3.6,33.1)
  Bottom Layer w0.15: v1(3.6,33.1) 3.708,33.1 4.713,32.095 U8.18@4.724,32.095
STLK_ON: R1.1 R4.2 U8.43 | length 21.8
  Bottom Layer w0.15: R1.1@-1.853,30.767 R1.1@-1.847,30.773 ; R4.2@-1.847,32.062 R1.1@-1.847,30.773 ; U8.43@15.967,33.509 15.213,32.755 15.213,32.166 14.86,31.812 11.834,31.812 11.234,32.412 8.753,32.412 7.003,30.662 5.203,30.662 5.003,30.462 5.003,30.455 4.71,30.162 4.095,30.162 3.245,31.012 -1.608,31.012 R1.1@-1.847,30.773
STLK_RX: CN2.2 R23.2 U5.13 | length 12.7
  Top Layer w0.15: R23.2@23.103,47.462 CN2.2@24.523,47.462
  Bottom Layer w0.15: U5.13@17.753,53.012 19.803,53.012 20.203,53.412 21.053,53.412 21.703,52.762 21.703,51.363 22.753,50.313 22.753,49.138 23.378,48.512 24.153,48.512 24.553,48.112 CN2.2@24.553,47.492
STLK_SWCLK: R37.2 SB3.2 U8.46 | length 29.6
  Top Layer w0.15: v1(20.603,52.912) 21.153,52.362 21.153,47.266 22.828,45.591 22.828,40.715 23.84,39.702 v1(23.84,39.27)
  L3 w0.15: v1(21.595,39.62) 23.49,39.62 v1(23.84,39.27)
  Bottom Layer w0.15: R37.2@17.005,34.805 17.082,34.729 17.789,34.729 ; U8.46@17.028,32.448 18.003,33.423 18.003,34.515 ; R37.2@17.103,34.912 R37.2@17.107,34.907 ; v1(20.603,52.912) 20.603,52.162 SB3.2@20.753,52.012 ; v1(21.595,39.62) 21.595,39.495 20.285,38.185 19.343,38.185 18.613,37.455 18.613,36.502 18.97,36.145 18.97,35.696 18.003,34.729 ; 17.789,34.729 18.003,34.515 ; 17.789,34.729 18.003,34.729 ; 18.003,34.515 18.003,34.729
STLK_SWDIO: SB2.2 U8.45 | length 12.6
  Top Layer w0.15: v1(17.153,43.312) 18.153,42.312 18.153,35.812 17.503,35.162 v1(17.503,33.662)
  Bottom Layer w0.15: U8.45@16.674,32.802 v1@17.519,33.646 ; SB2.2@17.003,42.312 17.153,42.462 v1(17.153,43.312)
STLK_TX: CN2.1 R22.1 U5.12 | length 14.7
  Top Layer w0.15: R22.1@23.103,50.032 CN2.1@24.553,50.032
  Bottom Layer w0.15: U5.12@16.253,54.162 16.822,54.162 17.572,53.412 18.996,53.412 19.096,53.312 19.672,53.312 20.072,53.712 21.177,53.712 22.003,52.887 22.003,51.487 23.053,50.437 23.053,49.262 23.453,48.862 24.103,48.862 24.553,49.312 CN2.1@24.553,50.032
STM_JTCK: CN4.2 U5.37 | length 37.8
  Top Layer w0.15: v1(13.303,48.912) 15.524,48.912 16.503,47.934 16.503,44.712 18.453,42.762 18.453,31.262 17.453,30.262 17.453,26.979 18.453,25.979 18.453,23.312 18.651,23.114 CN4.2@18.651,20.11
  Bottom Layer w0.15: U5.37@9.253,47.512 10.403,47.512 11.503,48.612 13.003,48.612 v1(13.303,48.912)
STM_JTMS: CN4.4 U5.34 | length 39.8
  Top Layer w0.15: v1(11.753,47.062) 11.753,45.912 12.603,45.062 12.603,43.948 11.603,42.948 11.603,42.162 12.553,41.212 16.903,41.212 17.853,40.262 17.853,35.937 17.003,35.087 17.003,31.662 17.353,31.312 17.353,30.587 17.153,30.387 17.153,26.808 17.21,26.75 17.257,26.75 18.153,25.855 18.153,23.362 15.059,20.268 CN4.4@15.059,16.518
  Bottom Layer w0.15: U5.34@11.753,46.012 v1(11.753,47.062)
STM_RST: C26.2 JP1.1 Q2.3 R17.1 U5.7 | length 27.4
  Top Layer w0.15: v1(13.353,53.362) 13.753,53.762 R17.1@13.753,55.312
  L3 w0.15: v1(13.353,53.362) 13.353,60.212 15.053,61.912 v1(16.803,61.912)
  Bottom Layer w0.15: v1(13.353,53.362) 13.753,53.762 U5.7@13.753,54.512 13.753,55.262 13.453,55.562 C26.2@13.453,55.862 ; v1(16.803,61.912) 17.103,62.212 20.253,62.212 21.433,63.392 JP1.1@24.453,63.392 24.453,61.762 24.853,61.362 Q2.3@24.853,60.312
T_JTCK: SB3.1 U5.15 U5.26 | length 10.4
  Bottom Layer w0.15: U5.26@15.753,46.012 15.753,47.762 15.303,48.212 15.303,51.712 15.603,52.012 U5.15@17.753,52.012 SB3.1@19.653,52.012
T_JTMS: R19.1 SB2.1 U5.27 | length 4.3
  Bottom Layer w0.15: U5.27@15.253,46.012 15.253,44.812 R19.1@15.403,44.662 15.403,42.312 SB2.1@15.903,42.312
T_NRST: SB4.1 U5.18 | length 1.9
  Bottom Layer w0.15: U5.18@17.753,50.512 SB4.1@19.653,50.512
T_SWDIO_IN: R19.2 U5.25 | length 1.4
  Bottom Layer w0.15: U5.25@16.253,46.012 16.253,44.712 R19.2@16.303,44.662
TX1_N: CN5.A3 CN7.A3 | length 10.2
  Top Layer w0.152: CN5.A3@-12.337,59.499 -11.211,59.499 -10.861,59.149 -10.35,59.149 v2(-10.297,59.201)
  L2-GND w0.202: v2(-10.297,59.201) -10.248,59.152 -9.949,59.152 -9.659,59.442 -9.659,60.592 -7.396,62.855 -6.296,62.855 -5.646,63.505 -5.646,64.205 v2(-5.74,64.299)
TX1_P: CN5.A2 CN7.A2 | length 10.7
  Top Layer w0.152: CN5.A2@-12.337,58.499 -11.211,58.499 -10.865,58.844 -10.35,58.844 v2(-10.297,58.791)
  L2-GND w0.202: v2(-10.297,58.791) -10.248,58.84 -9.819,58.84 -9.347,59.312 -9.347,60.462 -7.267,62.543 -6.167,62.543 -5.334,63.376 -5.334,64.205 v2(-5.24,64.299)
TX2_N: CN5.B3 CN7.B3 | length 17.2
  Top Layer w0.152: v2(-14.197,54.204) -14.145,54.151 -13.881,54.151 -13.533,54.499 CN5.B3@-12.457,54.499 CN5.B3@-12.407,54.499
  L2-GND w0.202: v2(-14.197,54.204) -14.246,54.155 -15.007,54.155 -15.177,54.325 -15.177,55.083 -14.837,55.423 -14.837,58.019 -13.197,59.659 -13.197,61.029 -10.135,64.09 -10.135,64.43 -9.084,65.482 -9.084,65.805 v2(-8.99,65.899)
TX2_P: CN5.B2 CN7.B2 | length 17.7
  Top Layer w0.152: v2(-14.197,53.794) -14.145,53.846 -13.881,53.846 -13.533,53.499 CN5.B2@-12.457,53.499 CN5.B2@-12.407,53.499
  L2-GND w0.202: v2(-14.197,53.794) -14.246,53.843 -15.136,53.843 -15.489,54.195 -15.489,55.212 -15.149,55.552 -15.149,58.148 -13.509,59.788 -13.509,61.158 -10.447,64.219 -10.447,64.559 -9.396,65.611 -9.396,65.805 v2(-9.49,65.899)
USB_RENUMn: R25.2 U5.38 | length 16
  L3 w0.15: v1(11.85,49.46) 14.4,49.46 17.903,52.962 v1(17.903,57.312)
  Bottom Layer w0.15: U5.38@9.253,48.012 10.403,48.012 v1(11.85,49.46) ; v1(17.903,57.312) R25.2@18.803,57.312
USB_STLK_ID: CN3.4 R34.2 | length 2.3
  Top Layer w0.15: R34.2@22.703,57.212 22.703,56.312 23.066,55.949 CN3.4@23.963,55.949
USB_STLK_N: CN3.2 U5.32 U7.1 U7.6 | length 19.3
  Top Layer w0.152: v1(12.83,47.79) 12.653,47.968 12.653,49.123 12.656,49.126 12.656,49.794 12.653,49.797 12.653,51.507 14.953,53.807 14.953,54.624 15.153,54.824 16.365,54.824 16.789,54.4 17.267,54.4 17.343,54.476 U7.6@17.973,54.476 U7.1@19.583,54.476 20.248,54.476 20.3,54.425 20.915,54.425 21.312,54.821 23.039,54.821 23.212,54.649 CN3.2@23.963,54.649
  Bottom Layer w0.152: U5.32@12.753,46.012 12.753,46.689 12.653,46.789 12.653,47.612 v1(12.83,47.79)
USB_STLK_P: CN3.3 R29.1 U5.33 U7.3 U7.4 | length 19.8
  Top Layer w0.152: v1(12.17,47.79) 12.348,47.968 12.348,49.249 12.351,49.252 12.351,49.667 12.348,49.671 12.348,51.633 14.648,53.933 14.648,54.774 15.003,55.129 16.365,55.129 16.789,55.552 17.267,55.552 17.343,55.476 U7.4@17.973,55.476 U7.3@19.583,55.476 20.248,55.476 20.3,55.527 21.001,55.527 21.403,55.126 23.039,55.126 23.212,55.299 CN3.3@23.963,55.299
  Bottom Layer w0.152: v1(12.17,47.79) 12.348,47.612 12.348,46.784 12.253,46.689 U5.33@12.253,46.012
USBPD1_CC1: SB8.2 T3.4 T3.7 U8.36 | length 39.3
  L3 w0.15: v1(9.253,58.612) 9.253,58.062 8.028,56.837 3.928,56.837 3.578,56.487 3.578,55.088 4.703,53.963 4.703,49.462 5.56,48.605 5.56,43.148 8.295,40.412 v1(14.453,40.412)
  Bottom Layer w0.15: T3.7@6.703,57.512 8.54,57.512 SB8.2@8.59,57.462 ; SB8.2@8.603,57.462 8.603,58.162 9.053,58.612 v1(9.253,58.612) ; U8.36@13.492,35.984 13.492,36.027 14.203,36.738 14.203,39.462 14.453,39.712 v1(14.453,40.412)
USBPD1_CC2: SB7.2 T2.4 T2.7 U8.35 | length 32.4
  L3 w0.15: v1(4.103,57.462) 3.278,56.637 3.278,54.964 4.403,53.839 4.403,49.338 5.26,48.481 5.26,43.024 8.171,40.112 13.703,40.112 v1(13.903,39.912)
  Bottom Layer w0.15: T2.7@1.165,57.512 T2.4@1.99,57.512 3.003,57.512 SB7.2@3.053,57.462 v1(4.103,57.462) ; U8.35@13.139,36.337 13.903,37.101 13.903,39.813 13.853,39.863 v1(13.903,39.912)
VBUS_N: CN7.A4 CN7.A9 CN7.B4 CN7.B9 R48.1 U10.12 | length 25.5
  Top Layer w0.25: CN7.B4@-8.49,65.899 -8.49,65.324 -8.74,65.074 CN7.A9@-8.74,64.299 -8.74,62.502 -7.997,61.759 v1(-7.997,61.012) ; CN7.B9@-5.99,65.899 -5.99,65.324 -6.24,65.074 -6.24,62.824 -4.978,61.562 v1(-4.647,61.562)
  L3 w0.202: -6.747,60.962 -6.697,61.012
  L3 w0.25: v1(-7.997,61.012) -6.697,61.012 -6.147,61.562 v1(-4.647,61.562) ; v1(-6.747,56.962) -6.747,60.962
  Bottom Layer w0.15: U10.12@-4.997,58.962 U10.12@-4.797,58.962
  Bottom Layer w0.152: R48.1@-8.261,56.962 -8.247,56.962 -8.247,58.013 -7.947,58.312 -7.147,58.312 -5.947,59.512 -5.047,59.512 -4.797,59.262 U10.12@-4.797,58.962
  Bottom Layer w0.3: R48.1@-8.247,56.962 v1(-6.747,56.962)
VBUS_P: C13.2 C14.2 CN5.A4 R8.2 R48.2 U3.10 U3.14 U10.11 U10.13 U14.1 VBUS.1 | length 50.4
  Top Layer w0.25: v1(-9.647,58.262) -9.197,58.712 v1(-5.797,58.712)
  Top Layer w0.3: CN5.A4@-12.457,40.899 -10.247,40.899 ; -10.247,35.662 -10.247,40.899 ; v1(-9.647,40.899) -10.247,40.899
  Bottom Layer w0.152: R48.2@-8.261,60.012 -8.261,58.915 -7.963,58.617 -7.274,58.617 -6.074,59.817 -4.902,59.817 -4.697,59.612 U10.13@-4.347,59.612
  Bottom Layer w0.25: R8.2@-10.897,26.3 v1(-10.897,32.862) v1(-10.897,33.462) ; v1(-5.797,58.712) -5.547,58.462 U10.11@-4.997,58.462
  Bottom Layer w0.3: VBUS.1@-12.097,38.312 -10.397,38.312 -9.647,39.062 v1(-9.647,40.899) v1(-9.647,58.262) -9.647,59.112 -8.747,60.012 R48.2@-8.261,60.012
VCP_RX: R22.2 U8.1 | length 43.4
  Top Layer w0.15: R22.2@23.103,49.112 22.578,49.112 22.378,48.912 22.028,48.912 21.753,48.637 21.753,47.515 23.428,45.84 23.428,40.963 24.703,39.688 24.703,25.481 24.034,24.812 23.903,24.812 v1(23.603,24.512)
  Bottom Layer w0.15: U8.1@10.128,24.009 10.457,23.68 11.803,23.68 13.77,21.712 17.477,21.712 20.727,24.962 22.677,24.962 22.827,24.812 23.303,24.812 v1(23.603,24.512)
VCP_TX: R23.1 U8.64 | length 41.5
  Top Layer w0.15: R23.1@23.103,48.412 22.578,48.412 22.378,48.612 22.153,48.612 22.053,48.512 22.053,47.639 23.728,45.964 23.728,41.087 25.003,39.812 25.003,25.062 v1(24.503,24.562)
  Bottom Layer w0.15: U8.64@12.078,24.034 U8.64@12.431,23.68 14.099,22.012 17.353,22.012 20.603,25.262 22.801,25.262 22.951,25.112 23.953,25.112 v1(24.503,24.562)
VDD: C45.2 C46.2 C47.2 CN1.1 CN6.2 CN9.1 L2.1 SB6.2 U8.6 U8.8 | length 121.8
  Top Layer w0.3: v1(8.353,28.412) 8.353,30.712 v1(9.053,31.412) ; v1(9.203,26.212) 9.684,26.212 L2.1@10.568,27.097 11.408,27.936 C47.2@11.408,28.017 ; v1(16.153,14.962) 16.803,14.962 20.903,19.062 22.953,19.062 24.195,17.82 24.195,15.555 22.003,13.362 CN9.1@22.003,9.862
  L3 w0.3: CN6.2@2.323,66.412 2.323,64.582 1.003,63.262 1.003,49.512 2.828,47.687 2.828,47.225 2.828,46.3 2.981,46.146 2.981,44.445 2.828,44.291 2.825,44.288 2.825,43.227 2.831,43.221 2.831,41.521 5.703,38.649 5.703,37.137 6.8,36.039 6.8,32.4 7.788,31.412 v1(9.053,31.412) 9.9,32.26 9.9,38.387 10.125,38.612 10.125,38.848 10.914,39.637 13.25,39.637 13.55,39.337 14.191,39.337 15.653,40.8 20.4,40.8 21.05,41.45 21.05,43.312 CN1.1@19.763,44.599 ; v1(8.353,28.412) 8.353,26.612 8.753,26.212 v1(9.203,26.212) 9.203,24.176 12.506,20.872 12.506,14.716 v1(12.003,14.212)
  Bottom Layer w0.3: SB6.2@1.653,64.212 2.323,64.882 CN6.2@2.323,66.412 ; C46.2@5.184,24.847 5.325,24.847 v1(5.785,25.307) 6.04,25.562 6.606,25.562 U8.8@7.199,26.155 8.353,27.309 v1(8.353,28.412) ; C45.2@5.82,24.211 v1@6.315,24.706 ; v1(6.35,24.741) 7.199,24.741 U8.6@7.906,25.448 8.67,26.212 v1(9.203,26.212) ; v1(12.003,14.212) 14.703,14.212 15.453,14.962 v1(16.153,14.962)
VREF+: C48.2 C49.2 L2.2 U8.7 | length 5.8
  Top Layer w0.3: v1(8.963,27.212) 8.963,27.754 L2.2@9.437,28.228 9.437,28.297 C49.2@10.258,29.117 10.208,29.117 C48.2@9.308,30.017
  Bottom Layer w0.3: U8.7@7.552,25.802 v1(8.963,27.212)
pads on no net: B2.NPTH1 B2.NPTH2 CN7.H1 CN7.H2 CN7.M1 CN7.M2 CN7.M3 TARGET1.1 TARGET2.1 TARGET3.1 TARGET4.1 U1.3 U1.5 U5.4 U5.11 U5.14 U5.16 U5.17 U5.19 U5.21 U5.22 U5.31 U5.40 U5.41 U5.42 U5.43 U5.45 U5.46 U9.H1 U10.0 U10.6 U10.7 U10.8 U10.14 U10.15 U10.16 U11.0 U11.6 U11.7 U11.8 U11.14 U11.15 U11.16 U12.0 U12.6 U12.7 U12.8 U12.14 U12.15 U12.16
